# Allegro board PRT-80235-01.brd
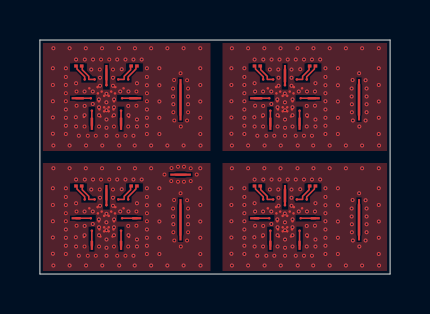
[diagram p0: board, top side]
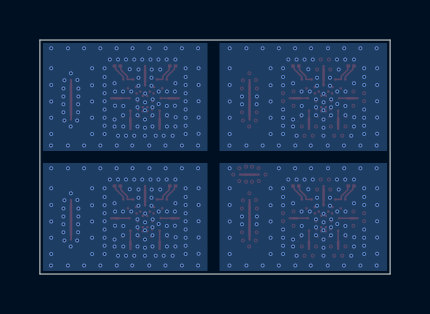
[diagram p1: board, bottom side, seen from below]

Outline 17.55 x 11.7 mm; copper layers: TOP, LAYER_2, LAYER_3, BOTTOM. Coordinates in mm from the lower left corner of the outline.
Outline path: 0,11.7 0,0 17.55,0 17.55,11.7 0,11.7

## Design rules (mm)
constraint set DEFAULT: min track width 0.1

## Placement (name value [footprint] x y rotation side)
NOREF  -  []  0 11.7 0 top
NOREF#2  -  []  -27.56 -53.3 0 top
NOREF#3  -  []  -14.84 -36.93 0 top
NOREF#4  -  []  58.85 55.85 0 top
NOREF#5  -  []  -36.15 50.85 0 top
NOREF#6  -  []  70.38 -67.66 0 top
NOREF#7  -  []  0 5.85 0 top
NOREF#8  -  []  8.85 11.7 0 top
NOREF#9  -  []  -201.42 85.57 0 top
NOREF#10  -  []  17.55 0 90 top
U1  IC_SHAGGY_DIE_33P_2  [IC_DIE_2440X2094_33]  3.33 2.81 0 top
U2  IC_SHAGGY_DIE_33P_2  [IC_DIE_2440X2094_33]  12.28 2.81 0 top
U3  IC_SHAGGY_DIE_33P_2  [IC_DIE_2440X2094_33]  3.33 8.81 0 top
U4  IC_SHAGGY_DIE_33P_2  [IC_DIE_2440X2094_33]  12.28 8.81 0 top

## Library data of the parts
U1-U4 = IC_SHAGGY_DIE_33P_2

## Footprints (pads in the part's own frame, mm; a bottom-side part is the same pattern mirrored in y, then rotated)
IC_DIE_2440X2094_33
  round 0.127 smd: 1(-0.592,0.913) 2(-1.091,0.913) 3(0.592,0.913) 4(1.091,0.913) 5(1.129,-0.959) 6(0.303,-0.94) 7(-0.303,-0.94) 8(-1.129,-0.959) 9(-1.091,-0.412) 10(-0.859,0.47) 11(-0.785,-0.027) 12(-0.732,-0.648) 13(-0.428,0.216) 14(-0.446,0.531) 15(-0.353,-0.585) 16(-0.379,-0.181) 17(-0.239,0.306) 18(-0.114,-0.68) 19(-0.114,-0.48) 20(-0.114,0.091) 21(0,0.629) 22(0.114,-0.68) 23(0.114,-0.48) 24(0.114,0.091) 25(0.239,0.306) 26(0.353,-0.585) 27(0.379,-0.181) 28(0.428,0.216) 29(0.446,0.531) 30(0.732,-0.648) 31(0.785,-0.027) 32(0.859,0.47) 33(1.091,-0.412)

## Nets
GND_1: U1.5 U1.6 U1.7 U1.8 U1.9 U1.10 U1.13 U1.14 U1.15 U1.16 U1.17 U1.18 U1.19 U1.20 U1.22 U1.23 U1.24 U1.25 U1.26 U1.27 U1.28 U1.29 U1.32 U1.33
GND_2: U2.5 U2.6 U2.7 U2.8 U2.9 U2.10 U2.13 U2.14 U2.15 U2.16 U2.17 U2.18 U2.19 U2.20 U2.22 U2.23 U2.24 U2.25 U2.26 U2.27 U2.28 U2.29 U2.32 U2.33
GND_3: U3.5 U3.6 U3.7 U3.8 U3.9 U3.10 U3.13 U3.14 U3.15 U3.16 U3.17 U3.18 U3.19 U3.20 U3.22 U3.23 U3.24 U3.25 U3.26 U3.27 U3.28 U3.29 U3.32 U3.33
GND_4: U4.5 U4.6 U4.7 U4.8 U4.9 U4.10 U4.13 U4.14 U4.15 U4.16 U4.17 U4.18 U4.19 U4.20 U4.22 U4.23 U4.24 U4.25 U4.26 U4.27 U4.28 U4.29 U4.32 U4.33
V1_1: U1.2
V1_2: U2.2
V1_3: U3.2
V1_4: U4.2
V2_1: U1.1
V2_2: U2.1
V2_3: U3.1
V2_4: U4.1
VDD_1: U1.4
VDD_2: U2.4
VDD_3: U3.4
VDD_4: U4.4
VSS_1: U1.3(VSS_EXT)
VSS_2: U2.3(VSS_EXT)
VSS_3: U3.3(VSS_EXT)
VSS_4: U4.3(VSS_EXT)
RF1_1: U1.11
RF1_2: U2.11
RF1_3: U3.11
RF1_4: U4.11
RF2_1: U1.12
RF2_2: U2.12
RF2_3: U3.12
RF2_4: U4.12
RF3_1: U1.30
RF3_2: U2.30
RF3_3: U3.30
RF3_4: U4.30
RF4_1: U1.31
RF4_2: U2.31
RF4_3: U3.31
RF4_4: U4.31
RFC_1: U1.21
RFC_2: U2.21
RFC_3: U3.21
RFC_4: U4.21

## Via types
v1: diameter 0.2, hole 0.102, TOP to BOTTOM, 438 vias
v2: diameter 0.2, hole 0.1, TOP to LAYER_2, 70 vias

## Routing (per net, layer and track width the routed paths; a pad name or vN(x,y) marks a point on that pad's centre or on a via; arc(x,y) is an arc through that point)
GND_1:
  vias: v1(0.67,5.29) v1(0.65,4.29) v1(0.65,3.45) v1(0.65,2.64) v1(0.65,1.82) v1(0.65,1.01) v1(0.67,0.42) v1(1.3,4.29) v1(1.3,3.85) v1(1.3,3.45) v1(1.3,2.22) v1(1.3,1.81) v1(1.3,1.41) v1(1.3,1) v1(1.49,5.29) v1(1.49,0.42) v1(1.81,4.72) v1(1.81,3.54) v1(1.8,1.84) v1(1.81,1.38) v1(1.95,0.91) v1(2.25,4.72) v1(2.24,3.12) v1(2.24,2.4) v1(2.24,1.94) v1(2.3,5.29) v1(2.31,0.42) v1(2.57,4.22) v1(2.66,4.72) v1(2.65,3.12) v1(2.65,2.5) v1(2.95,2.73) v1(2.96,2.34) v1(2.96,1.94) v1(3.01,3.81) v1(3.01,3.41) v1(3.11,5.29) v1(3.12,0.42) v1(3.33,3.01) v1(3.33,2.58) v1(3.34,2.19) v1(3.34,1.72) v1(3.34,1.31) v1(3.34,0.91) v1(3.66,3.81) v1(3.66,3.41) v1(3.72,2.73) v1(3.71,2.34) v1(3.71,1.94) v1(3.88,4.72) v1(3.96,5.29) v1(3.97,0.42) v1(4.1,4.24) v1(4.02,3.12) v1(4.29,4.72) v1(4.44,3.12) v1(4.43,2.4) v1(4.44,1.94) v1(4.69,4.72) v1(4.69,0.91) v1(4.76,5.29) v1(4.75,0.42) v1(4.86,3.54) v1(4.86,1.72) v1(4.86,1.38) v1(5.1,4.72) v1(5.36,4.29) v1(5.36,3.85) v1(5.36,3.44) v1(5.36,2.22) v1(5.36,1.81) v1(5.36,1.41) v1(5.36,1) v1(5.57,5.29) v1(5.57,0.42) v1(5.99,4.29) v1(5.99,3.44) v1(5.99,2.62) v1(5.99,1.81) v1(5.99,1) v1(6.39,0.42) v1(6.67,2.87) v1(6.69,2.49) v1(7.2,0.42) v1(7.42,2.87) v1(7.42,2.49) v1(8.04,5.29) v1(8.04,4.29) v1(8.04,3.45) v1(8.04,2.62) v1(8.04,1.81) v1(8.04,1) v1(8.05,0.42) v2(1.3,3.04) v2(1.3,2.64) v2(1.84,3.12) v2(1.84,2.41) v2(2.24,1.38) v2(2.4,0.91) v2(2.8,0.91) v2(2.96,1.38) v2(3.06,4.72) v2(3,4.22) v2(3.47,4.72) v2(3.66,4.22) v2(3.71,1.38) v2(3.88,0.91) v2(4.29,0.91) v2(4.42,1.38) v2(4.84,3.12) v2(4.84,2.41) v2(5.36,3.04) v2(5.36,2.64) v2(6.24,4.97) v2(6.59,5.3) v2(6.58,4.65) v2(6.67,3.27) v2(6.69,2.09) v2(6.72,3.7) v2(6.74,1.67) v2(6.92,5.36) v2(6.92,4.61) v2(7.05,4.04) v2(7.06,1.38) v2(7.22,5.36) v2(7.22,4.61) v2(7.38,3.69) v2(7.38,1.67) v2(7.42,3.27) v2(7.42,2.09) v2(7.56,5.29) v2(7.56,4.65) v2(7.86,4.97)
GND_2:
  vias: v1(9.6,4.29) v1(9.6,3.45) v1(9.6,2.64) v1(9.6,1.82) v1(9.6,1.01) v1(9.62,5.29) v1(9.62,0.42) v1(10.25,4.29) v1(10.25,3.85) v1(10.25,3.45) v1(10.25,3.04) v1(10.25,2.64) v1(10.25,2.22) v1(10.25,1.81) v1(10.25,1.41) v1(10.25,1) v1(10.43,5.29) v1(10.43,0.42) v1(10.76,4.72) v1(10.76,3.54) v1(10.78,3.12) v1(10.78,2.41) v1(10.75,1.84) v1(10.76,1.38) v1(10.9,0.91) v1(11.2,4.72) v1(11.18,3.12) v1(11.19,2.4) v1(11.18,1.94) v1(11.18,1.38) v1(11.25,5.29) v1(11.26,0.42) v1(11.35,0.91) v1(11.52,4.22) v1(11.6,3.12) v1(11.6,2.5) v1(11.61,4.72) v1(11.75,0.91) v1(11.9,2.73) v1(11.95,4.22) v1(11.96,3.81) v1(11.96,3.41) v1(11.91,2.34) v1(11.91,1.94) v1(11.91,1.38) v1(12.06,5.29) v1(12.01,4.72) v1(12.07,0.42) v1(12.27,3.02) v1(12.28,2.58) v1(12.28,2.19) v1(12.28,1.72) v1(12.28,1.31) v1(12.28,0.91) v1(12.42,4.72) v1(12.61,4.22) v1(12.61,3.81) v1(12.61,3.41) v1(12.66,2.73) v1(12.66,2.34) v1(12.66,1.94) v1(12.66,1.38) v1(12.82,4.72) v1(12.82,0.91) v1(12.91,5.29) v1(12.97,3.12) v1(12.92,0.42) v1(13.05,4.24) v1(13.23,4.72) v1(13.23,0.91) v1(13.38,3.12) v1(13.37,2.4) v1(13.38,1.94) v1(13.37,1.38) v1(13.63,4.72) v1(13.63,0.91) v1(13.7,0.42) v1(13.71,5.29) v1(13.78,3.12) v1(13.78,2.41) v1(13.81,3.54) v1(13.81,1.72) v1(13.81,1.38) v1(14.05,4.72) v1(14.31,4.29) v1(14.31,3.85) v1(14.31,3.44) v1(14.31,3.04) v1(14.31,2.64) v1(14.31,2.22) v1(14.31,1.81) v1(14.31,1.41) v1(14.31,1) v1(14.52,5.29) v1(14.52,0.42) v1(14.93,4.29) v1(14.93,3.44) v1(14.93,2.62) v1(14.93,1.81) v1(14.93,1) v1(15.33,5.29) v1(15.33,0.42) v1(15.67,3.7) v1(15.62,3.27) v1(15.62,2.87) v1(15.63,2.49) v1(15.63,2.09) v1(15.68,1.67) v1(16,4.04) v1(16.01,1.38) v1(16.15,5.29) v1(16.15,0.42) v1(16.32,3.69) v1(16.37,3.27) v1(16.37,2.87) v1(16.37,2.49) v1(16.37,2.09) v1(16.32,1.67) v1(16.98,5.29) v1(16.98,4.29) v1(16.98,3.45) v1(16.98,2.62) v1(16.98,1.81) v1(16.98,1) v1(17,0.42)
GND_3:
  vias: v1(0.67,11.29) v1(0.65,10.29) v1(0.65,9.45) v1(0.65,8.64) v1(0.65,7.82) v1(0.65,7.01) v1(0.67,6.42) v1(1.3,10.29) v1(1.3,9.85) v1(1.3,9.45) v1(1.3,8.22) v1(1.3,7.81) v1(1.3,7.41) v1(1.3,7) v1(1.49,11.29) v1(1.49,6.42) v1(1.81,10.72) v1(1.81,9.54) v1(1.8,7.84) v1(1.81,7.38) v1(1.95,6.91) v1(2.25,10.72) v1(2.24,9.12) v1(2.24,8.4) v1(2.24,7.94) v1(2.3,11.29) v1(2.31,6.42) v1(2.57,10.22) v1(2.66,10.72) v1(2.65,9.12) v1(2.65,8.5) v1(2.95,8.73) v1(2.96,8.34) v1(2.96,7.94) v1(3.01,9.81) v1(3.01,9.41) v1(3.11,11.29) v1(3.12,6.42) v1(3.33,9.01) v1(3.33,8.58) v1(3.34,8.19) v1(3.34,7.72) v1(3.34,7.31) v1(3.34,6.91) v1(3.66,9.81) v1(3.66,9.41) v1(3.72,8.73) v1(3.71,8.34) v1(3.71,7.94) v1(3.88,10.72) v1(3.96,11.29) v1(3.97,6.42) v1(4.1,10.24) v1(4.02,9.12) v1(4.29,10.72) v1(4.44,9.12) v1(4.43,8.4) v1(4.44,7.94) v1(4.69,10.72) v1(4.69,6.91) v1(4.76,11.29) v1(4.75,6.42) v1(4.86,9.54) v1(4.86,7.72) v1(4.86,7.38) v1(5.1,10.72) v1(5.36,10.29) v1(5.36,9.85) v1(5.36,9.44) v1(5.36,8.22) v1(5.36,7.81) v1(5.36,7.41) v1(5.36,7) v1(5.57,11.29) v1(5.57,6.42) v1(5.99,10.29) v1(5.99,9.44) v1(5.99,8.62) v1(5.99,7.81) v1(5.99,7) v1(6.39,11.29) v1(6.39,6.42) v1(6.67,8.88) v1(6.69,8.49) v1(7.2,11.29) v1(7.2,6.42) v1(7.42,8.88) v1(7.42,8.49) v1(8.04,11.29) v1(8.04,10.29) v1(8.04,9.45) v1(8.04,8.62) v1(8.04,7.81) v1(8.04,7) v1(8.05,6.42) v2(1.3,9.04) v2(1.3,8.64) v2(1.84,9.12) v2(1.84,8.41) v2(2.24,7.38) v2(2.4,6.91) v2(2.8,6.91) v2(2.96,7.38) v2(3.06,10.72) v2(3,10.22) v2(3.47,10.72) v2(3.66,10.22) v2(3.71,7.38) v2(3.88,6.91) v2(4.29,6.91) v2(4.42,7.38) v2(4.84,9.12) v2(4.84,8.41) v2(5.36,9.04) v2(5.36,8.64) v2(6.67,9.27) v2(6.69,8.09) v2(6.72,9.7) v2(6.74,7.67) v2(7.05,10.04) v2(7.06,7.38) v2(7.38,9.69) v2(7.38,7.67) v2(7.42,9.27) v2(7.42,8.09)
GND_4:
  vias: v1(9.6,10.29) v1(9.6,9.45) v1(9.6,8.64) v1(9.6,7.82) v1(9.6,7.01) v1(9.62,11.29) v1(9.62,6.42) v1(10.25,10.29) v1(10.25,9.85) v1(10.25,9.45) v1(10.25,9.04) v1(10.25,8.64) v1(10.25,8.22) v1(10.25,7.81) v1(10.25,7.41) v1(10.25,7) v1(10.43,11.29) v1(10.43,6.42) v1(10.76,10.72) v1(10.76,9.54) v1(10.78,9.12) v1(10.78,8.41) v1(10.75,7.84) v1(10.76,7.38) v1(10.9,6.91) v1(11.2,10.72) v1(11.18,9.12) v1(11.19,8.4) v1(11.18,7.94) v1(11.18,7.38) v1(11.25,11.29) v1(11.26,6.42) v1(11.35,6.91) v1(11.52,10.22) v1(11.6,9.12) v1(11.6,8.5) v1(11.61,10.72) v1(11.75,6.91) v1(11.9,8.73) v1(11.95,10.22) v1(11.96,9.81) v1(11.96,9.41) v1(11.91,8.34) v1(11.91,7.94) v1(11.91,7.38) v1(12.06,11.29) v1(12.01,10.72) v1(12.07,6.42) v1(12.27,9.02) v1(12.28,8.58) v1(12.28,8.19) v1(12.28,7.72) v1(12.28,7.31) v1(12.28,6.91) v1(12.42,10.72) v1(12.61,10.22) v1(12.61,9.81) v1(12.61,9.41) v1(12.66,8.73) v1(12.66,8.34) v1(12.66,7.94) v1(12.66,7.38) v1(12.82,10.72) v1(12.82,6.91) v1(12.91,11.29) v1(12.97,9.12) v1(12.92,6.42) v1(13.05,10.24) v1(13.23,10.72) v1(13.23,6.91) v1(13.38,9.12) v1(13.37,8.4) v1(13.38,7.94) v1(13.37,7.38) v1(13.63,10.72) v1(13.63,6.91) v1(13.7,6.42) v1(13.71,11.29) v1(13.78,9.12) v1(13.78,8.41) v1(13.81,9.54) v1(13.81,7.72) v1(13.81,7.38) v1(14.05,10.72) v1(14.31,10.29) v1(14.31,9.85) v1(14.31,9.44) v1(14.31,9.04) v1(14.31,8.64) v1(14.31,8.22) v1(14.31,7.81) v1(14.31,7.41) v1(14.31,7) v1(14.52,11.29) v1(14.52,6.42) v1(14.93,10.29) v1(14.93,9.44) v1(14.93,8.62) v1(14.93,7.81) v1(14.93,7) v1(15.33,11.29) v1(15.33,6.42) v1(15.67,9.7) v1(15.62,9.27) v1(15.62,8.88) v1(15.63,8.49) v1(15.63,8.09) v1(15.68,7.67) v1(16,10.04) v1(16.01,7.38) v1(16.15,11.29) v1(16.15,6.42) v1(16.32,9.69) v1(16.37,9.27) v1(16.37,8.88) v1(16.37,8.49) v1(16.37,8.09) v1(16.32,7.67) v1(16.98,11.29) v1(16.98,10.29) v1(16.98,9.45) v1(16.98,8.62) v1(16.98,7.81) v1(16.98,7) v1(17,6.42)

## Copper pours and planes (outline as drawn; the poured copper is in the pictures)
GND_1 on TOP: 0.15,0.15 0.15,5.55 8.55,5.55 8.55,0.15
GND_1 on BOTTOM, LAYER_2, LAYER_3: 0.15,5.55 0.15,0.15 8.55,0.15 8.55,5.55
GND_2 on TOP, BOTTOM, LAYER_2, LAYER_3: 9.15,0.15 9.15,5.55 17.4,5.55 17.4,0.15
GND_3 on TOP: 0.15,6.15 0.15,11.55 8.55,11.55 8.55,6.15
GND_3 on BOTTOM, LAYER_2, LAYER_3: 0.15,11.55 0.15,6.15 8.55,6.15 8.55,11.55
GND_4 on TOP, BOTTOM, LAYER_2, LAYER_3: 9.15,6.15 9.15,11.55 17.4,11.55 17.4,6.15

Small or netless copper shapes (teardrops, artwork), in the pictures only: 41 on TOP

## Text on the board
BOTTOM: LAYER 4 (SECONDARY SIDE) | L4
Board Geometry/Soldermask Bottom: SOLDER MASK (SECONDARY SIDE) | BM
Ref Des/Silkscreen Bottom: SILKSCREEN (SECONDARY SIDE) | BS
Board Geometry/Outline: BOARD OUTLINE (TOP VIEW) | BD
TOP: LAYER 1 (PRIMARY SIDE) | L1
Board Geometry/Soldermask Top: SOLDER MASK (PRIMARY SIDE) | TM
Ref Des/Silkscreen Top: SILKSCREEN (PRIMARY SIDE) | TS
LAYER_2: LAYER 2 (GND PLANE) | L2
LAYER_3: LAYER 3 (GND PLANE) | L3
PASTEMASK_BOTTOM: SOLDER PASTE (SECONDARY SIDE) | BP
PASTEMASK_TOP: SOLDER PASTE (PRIMARY SIDE) | TP
User.6: SOLDER PASTE PARTICAL SIZE" <40 MICROMETERS | SOLDER PASTE TYPE: SAC405 (SAC305 IS ACCEPTABLE) | SOLDER PASTE FLUX" NO-CLEAN FLUX | SOLDER PASTE STENCIL TYPE:LASER CUT | SOLDER PASTE STENCIL THICKNESS: < 3.6 MILS | 12. | 13. | 14. | 15. | 16.
User.7: TO PSEMI A MURATA COMPANY. THE INFORMATION IN
User.8: NOTES: UNLESS OTHERWISE SPECIFIED, ALL DIMENSIONS ARE IN METRIC | INTERPRET DIMENSIONS AND TOLERANCES PER ANSI Y14.5M. | GERBER FILES CONTAIN BOARD OUTLINE FOR ALIGNMENT PURPOSES, | REMOVE PRIOR TO FABRICATION. | FABRICATE PCB PER IPC-6012, LATEST REVISION, TYPE 3, CLASS 2. | THE DETAILED NOTES AND INSTRUCTIONS ON THIS DRAWING SUPERCEDE IPC REQUIREMENTS. | BARE BOARD ACCEPTANCE PER IPC-A-600, LATEST REVISION. | TRACE WIDTH/SPACE/VIA: | TRACE WIDTHS/SPACING TO BE WITHIN | MINIMUM TRACE WIDTH: | MINIMUM AIR GAP: | MINIMUM VIA PAD DIAMETER: | MATERIAL: | NUMBER OF ELECTRICAL LAYERS IS | MATERIALS AND OVERALL THICKNESS SEE STACKUP DETAIL. | LOAD BOARD AND PREPREG PER IPC-4101.  COPPER FOIL PER IPC-MF-150. | MATERIAL'S GLASS TRANSITION TEMPERATURE (Tg) SHALL BE A MINIMUM OF | 170  CENTIGRADE. | MATERIAL MUST MEET UL796 WITH A FLAMMABILITY RATING OF 94V-0 | VENDOR UL LOGO AND DATE CODE TO BE SCREENED ON THE BOTTOM SIDE. IF NO BOTTOM | SILKSCREEN PROVIDED VENDOR MAY ADD BOTTOM SILKSCREEN. | TOLERANCES: | 6A. LAYER TO LAYER REGISTRATION WITHIN .076mm. | 6B. ALL HOLES TO BE LOCATED WITHIN .076mm OF ORIGINAL CAD DATA. | 6C. ALL HOLES SURROUNDED BY COPPER SHALL HAVE A MINIMUM ANNULAR RING OF .076mm. | 6D. ALL PLATED THROUGH HOLES TO HAVE A MINIMUM .015mm OF PLATING. | 6E. HOLE DIMENSIONS AND TOLERANCES APPLY AFTER PLATING, SEE DRILL HOLE CHART. | 6F. WARP AND TWIST NOT TO EXCEED .254 MM/MM. | 6G. CONDUCTOR WIDTHS/SPACINGS TO BE WITHIN | PLATING OPTIONS: USE 7A | 7A. IAg - IMMERSION SILVER 6-20 MICROINCHES MINIMUM PER IPC-4553. | 7B. SELECTIVE HARD GOLD FINISH IN THE DUT AND POGOPAD AREA(S), CLASS 1 50-100 MICROINCHES | 7C. HASL (HOT AIR SOLDER LEVEL) SMT PADS MUST BE FLAT TO A MAX OF .076mm (.003") ABOVE | APPLY LPI (LIQUID PROTO-IMAGEABLE) SOLDERMASK OVER BARE COPPER (SMOBC) PER IPC-SM-840 | CLASS "T" TO BOTH SIDES OF PCB. SOLDERMASK COLOR TO BE: GREEN | GERBER FILES REFLECT A ZERO OVERSIZE. VENDOR MAY OVERSIZE AS NEEDED, MAX THICKNESS | .015mm. IT IS NOT ACCEPTABLE FOR SOLDERMASK WEBBING TO DISAPPEAR BETWEEN FINE PITCH BALL PADS. | APPLY SILKSCREEN LEGEND USING WHITE NON-CONDUCTIVE EPOXY INK. TRIM SILKSCREEN FROM ALL | EXPOSED COPPER. | VENDOR TO REMOVE NON-FUNCTIONAL PADS FROM INTERNAL LAYERS. | VENDOR MAY ONLY ADD THIEVING OUTSIDE THE BOARD OUTLINE TO COMPENSATE FOR LOW COPPER DENSITY. | REMOVE ALL BURRS AND BREAK SHARP EDGES, INSIDE CORNER MAXIMUM RADIUS 381mm. | BARE BOARD ELECTRICAL TEST IS REQUIRED. USE THE SUPPLIED IPC-D-356 NETLIST "PRT-80235-01.IPC". | MATRIX DRAWING: USE 14A | 14A. NO MATRIX DRAWING IS REQUIRED. BOARDS TO BE DELIVERED FULLY ROUTED. | 14B. MATRIX DRAWING PROVIDED, SEE FABRICATION DRAWING SHEET 2 OF 2. | 14C. VENDOR TO GENERATE MATRIX DRAWING. VENDOR GENERATED MATRIX DRAWINGS REQUIRE APPROVAL | PLANARITY:  USE 15A,15B. | 15A. VARIATION OF BUMP PADS IN THE Z AXIS TO BE <=5um. | 15B. ALL VIAS TO BE NON-CONDUCTIVE EPOXY FILLED AND COPPER OVERPLATED AFTER PLATING AND BEFORE FINAL | 15C. ALL OTHER VIAS ARE TO BE PLUGGED AND FILLED WITH SOLDERMASK MATERIAL. | CONTROLLED IMPEDANCE REQUIREMENTS: | VENDOR MAY MODIFY DIELECTRIC THICKNESS BY 25% WITHOUT WRITTEN CONSENT. ANY MODIFICATION | GREATER THAN 25% REQUIRES WRITTEN CONSENT FROM PSEMI. | 16A. NO CONTROLLED IMPEDANCE MEASUREMENTS REQUIRED. | 16B. VENDOR TO PROVIDE TEST COUPON AND IMPEDANCE REPORT. | SHORTS DESIGNED IN BOARD: | NET XXXXXXXXXXXX. | NET XXXXXX TO GND, LAYER 4 | IPC-2221 TEST COUPONS A & B REQUIRED. TEST COUPONS SHALL BE IDENTIFIED AND TRACEABLE TO THE LOT. | TEST COUPONS, DATA, CROSSECTIONS VERIFYING WIDTH AND CERTIFICATES OF CONFORMANCE | SHALL ACCOMPANY ALL SHIPMENTS. MATERIAL VERIFICATION SHALL ALSO BE SENT IN WRITING. | SHIPMENTS WITHOUT THESE CERTIFICATIONS WILL NOT BE ACCEPTED. | DEVIATIONS BY FABRICATION FACILITY TO BE REPORTED TO PSEMI. | 0.10 - 0.20 uM OVER ELECTROLESS PALLADIUM OVER 3-6 uM OF PALLADIUM PER IPC-4552. | MICROINCHES THICK (KNOOP HARDNESS 130-200) OVER NICKEL PLATE IN ACCORDANCE WITH | IPC-A-600, LATEST REVISION, SECTION 4.0, CLASS 3 (200-600 MICROINCHES THICK). | FABRICATE IN ACCORDANCE WITH IPC-6018, START WITH 1/4oz. COPPER | SURFACE. HASL FINISH TO BE USED ON TEST OR PROTOTYPE BOARDS ONLY. THIS FINISH DOES | NOT COMPLY WITH RoHS DIRECTIVES. | 0.4572mm TRACES ON LAYER 1 ARE 50 OHMS, TRANSMISSION LINES_X_+/-5%. | .XXmm (.XXX") TRACES ON LAYER Y ARE 50 OHMS, MICROSTRIP, +/- 10%. | .XXmm (.XXX") TRACES ON LAYER Y ARE 100 OHMS, DIFFERENTIAL, +/- 10%. | BY PSEMI. PANELIZED BOARDS TO HAVE SAME ORIENTATION AND SHALL BE | ROUTED AND RETAINED WITH BREAK AWAY TABS. SEE DETAIL B. SUPPORT RAIL WIDTH TO BE | 6.35mm - 12.7mm WITH 1.52mm FIDUCIALS AND 3.175mm | TOOLING HOLES IN 3 CORNERS, PANELIZED SOLDERPASTE GERBER TO BE SUBMITTED TO | PSEMI. | SURFACE FINISH. NON-CONDUCTIVE EPOXY (SAN_EI 900 OR EQUIVALENT) IS RECOMMENDED. | EPOXY SHALL NOT PROTRUDE FROM HOLES. THIS APPLIES TO ALL VIAS THAT ARE EXPOSED ON | BOTH SIDES. A SMOOTH COPLANAR FINISH IS REQUIRED WHEN EXPOSED BY SOLDERMASK. | OUTER LAYERS= | INNER LAYERS= | SIDE. | 0.10mm | 0.05592 | NA | 4 | 0.0852mm | 20%. | 20% OF GERBER DATA. | USE 16A | 10%. | 20% OF GEBER DATA. | TOP | NO | 1. | 2. | 3. | 4. | 5. | 6. | 7. | 8. | 9. | 10. | 11. | 12. | 13. | 14. | 15. | 16. | 17. | 18. | 19.
User.9: TOLERANCES UNLESS OTHERWISE NOTED | DIMENSIONS IN mm/[Inches] | X.X | X.XX | X.XXX | X.XXXX | ANGLES | = +/- .2.5/[.1] | = +/- .25/[.01] | = +/- .127/[.005] | = +/- .0127/[.0005] | = +/- 1/2 DEG | OF | THIS DOCUMENT CONTAINS INFORMATION PROPRIETARY TO | PSEMI. THE INFORMATION IN THIS DOCUMENT IS NOT TO | BE USED OR DUPLICATED IN ANY MANNER WITHOUT THE | PRIOR APPROVAL OF PSEMI. | MATERIAL | FINISH | DO NOT SCALE DRAWING | CONTRACT NO. | DRAWN | CHECKED | ISSUED | REVISIED BY | ZONE | APPROVALS | REV | DATE | COMPANY | TITLE | SIZE | SCALE: | RoHS COMPLIANCE | RELEASE DATE | REVISIONS | DWG NO. | 9380 Carroll Park Drive | San Diego, CA, 92121 | (858)731-9400 Phone | (858)731-9499 Fax | SHEET: | SH | 07/08/21 | R.MARROQUIN | R.ALIDIO | 01 | 1 | NONE | PCB, | PE42546 Shaggy Probe Board | B | PRT-80235 | D | C | A | 4 | 3 | 2
User.10: TOLERANCES UNLESS OTHERWISE NOTED | DIMENSIONS IN mm/[Inches] | X.X | X.XX | X.XXX | X.XXXX | ANGLES | = +/- .2.5/[.1] | = +/- .25/[.01] | = +/- .127/[.005] | = +/- .0127/[.0005] | = +/- 1/2 DEG | OF | THIS DOCUMENT CONTAINS INFORMATION PROPRIETARY TO | PSEMI. THE INFORMATION IN THIS DOCUMENT IS NOT TO | BE USED OR DUPLICATED IN ANY MANNER WITHOUT THE | PRIOR APPROVAL OF PSEMI. | MATERIAL | FINISH | DO NOT SCALE DRAWING | CONTRACT NO. | DRAWN | CHECKED | ISSUED | REVISIED BY | ZONE | APPROVALS | REV | DATE | COMPANY | TITLE | SIZE | SCALE: | RoHS COMPLIANCE | RELEASE DATE | REVISIONS | DWG NO. | 9380 Carroll Park Drive | San Diego, CA, 92121 | (858)731-9400 Phone | (858)731-9499 Fax | SHEET: | SH | 07/08/21 | R.MARROQUIN | R.ALIDIO | 01 | 1 | NONE | PCA, | PE42546 Shaggy Probe Board | B | PRT-80234 | D | C | A | 4 | ASSEMBLY PRIMARY SIDE | 3 | ASSEMBLY SECONDARY SIDE | 2
User.11: THIS DOCUMENT CONTAINS INFORMATION PROPRIETARY TO | PSEMI. THE INFORMATION IN THIS DOCUMENT IS NOT TO | BE USED OR DUPLICATED IN ANY MANNER WITHOUT THE | PRIOR APPROVAL OF PSEMI. | REV | OF | SH | SHEET: | DWG NO. | RoHS COMPLIANCE | RELEASE DATE | SIZE | SCALE: | 2 | NONE | 01 | PRT-77450 | PRT-80235 | B | D | C | A | 1 | 3 | 4
User.27: FIGURE | FINISHED_SIZE | 0.1016 | DRILL CHART: TOP to BOTTOM | ALL UNITS ARE IN MILLIMETERS | TOLERANCE_DRILL | +0.0/-0.1016 | PLATED | QTY | 438
User.31: FIGURE | FINISHED_SIZE | 0.1 | DRILL CHART: TOP to LAYER_2 | ALL UNITS ARE IN MILLIMETERS | TOLERANCE_DRILL | +0.0/-0.1 | PLATED | QTY | 70
